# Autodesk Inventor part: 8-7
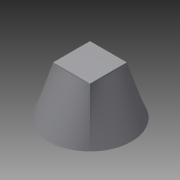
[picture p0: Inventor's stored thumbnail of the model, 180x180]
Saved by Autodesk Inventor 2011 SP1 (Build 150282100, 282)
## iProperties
Created: 2014-01
Part Number: 8-7
Document SubType Name: Modeling
Designer: Administrator
Density: 1 g/cm^3
Author: Administrator
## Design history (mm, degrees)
sketch "草图1"
  geometry: C1 r 22.5 at (0, 0); 1 further point
  constraints: 1 centre point, 1 coincident
  dimensions: "d0" = 45 diameter of C1
node "工作平面1"
sketch "草图2"
  geometry: L1 (-10, -10)-(10, -10); L2 (10, -10)-(10, 10); L3 (10, 10)-(-10, 10); L4 (-10, 10)-(-10, -10); 3 further points
  constraints: 8 end point, 2 midpoint, 2 parallel, 1 horizontal, 1 horizontal alignment, 1 perpendicular, 1 vertical alignment
  dimensions: "d2" = 20 distance of L3.end L2.end; "d3" = 20 distance of L2.end L1.end
feature "放样1" sketch "草图2" dims "d4" = 0, "d5" = 90 deg, "d6" = 0, "d7" = 90 deg
node "实体1"
other parameters: "d1" = 26
